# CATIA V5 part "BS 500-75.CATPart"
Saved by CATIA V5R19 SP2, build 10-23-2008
Part number: BS 500-75
Bounding box of the stored display mesh (mm): x -18.951 to 18.951, y -18.952 to 18.952, z 0 to 180
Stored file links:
  C:\Users\Bora\Desktop\3D Katı model\BS serisi\BS 500\BS 500-75.CATPart
  C:\Program Files\Dassault Systemes\B19\intel_a\reffiles\standard\MetricThickPitch.txt
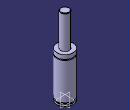
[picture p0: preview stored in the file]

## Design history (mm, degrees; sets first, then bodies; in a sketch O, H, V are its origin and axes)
Body1 (main body)
  Sketch1 on yz-plane, origin (0, 0, 0), H (0, 1, 0), V (0, 0, 1)
    point P1 (10, 179)
    point P3 (10, 179)
    point P5 (19, 94.5)
    point P6 (19, 92.5)
    point P9 (19, 94.5)
    point P14 (19, 92.5)
    line L1 (10, 179) -> (10, 104)
    arc A1 centre (9, 179) radius 1 from (10, 179) to (9, 180) ccw
    arc A2 centre (19, 93.5) radius 1 from (19, 94.5) to (19, 92.5) ccw
    line L2 (19, 0) -> (19, 4)
    line L3 (19, 94.5) -> (19, 104)
    line L4 (17, 7.5) -> (17, 4)
    line L5 (19, 7.5) -> (19, 92.5)
    line L6 (9, 180) -> (0, 180)
    point P15 (0, 180)
    line L7 (10, 104) -> (19, 104)
    line L8 (0, 0) -> (19, 0)
    line L9 (17, 7.5) -> (19, 7.5)
    line L10 (17, 4) -> (19, 4)
    coincidence: P15 V, P1 P3, P5 P9, P6 P14
    tangency: L6 A1
    horizontal: L7 H, L8 H, L9 H, L10 H
  Shaft1: profile Sketch1, axis Sketch1.V, angle 360
  Sketch2 on face of Shaft1 from Sketch1.L8, origin (0, 0, 0), H (1, 0, 0), V (0, -1, 0)
    point P1 (0, 0)
  Hole1: placed by Sketch2, at (0, 0, 0) direction (0, 0, 1), diameter 6.647, depth 4, threaded "M8", thread diameter 8, thread depth 4, pitch 1.25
